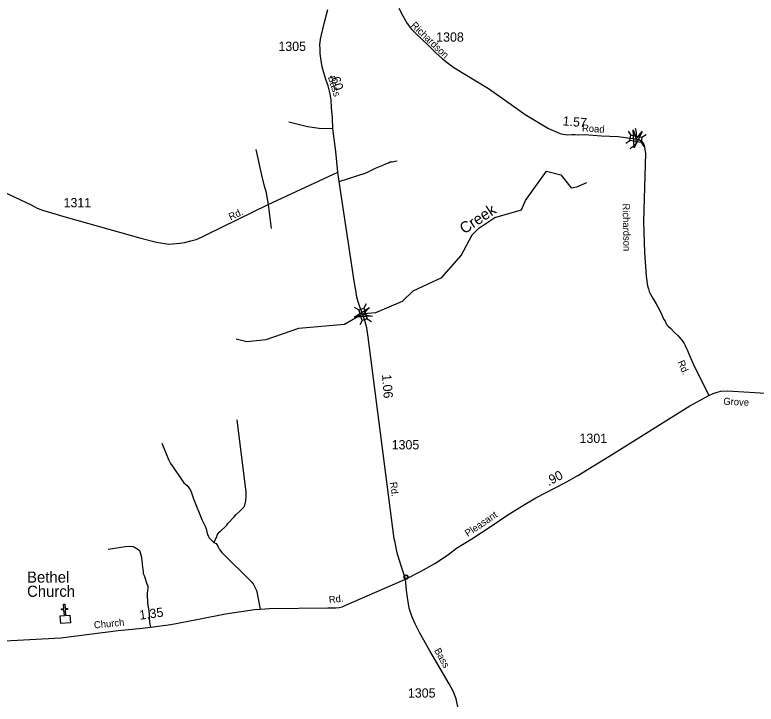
# Model space of a CAD drawing. Extents: x 2220236 to 2384410, y 720751 to 894131.
# Drawn here: x 2267334 to 2277319, y 812774 to 822056 of the extents above; entities that cross this region are included whole.
import ezdxf

# ---------------------------------------------------------------- set-up
doc = ezdxf.new("R2010")
doc.units = 0
doc.layers.add('Default', color=7, linetype='Continuous')

msp = doc.modelspace()

# ---------------------------------------------------------------- linework, layer by layer
at = {"layer": 'Default'}
for p, q in [((2275592.8, 820491.3), (2275632, 820434.5)), ((2275780.5, 820406.9), (2275837.3, 820446.1)), ((2275562.4, 820325.9), (2275619.2, 820365.1)), ((2275768.1, 820339.1), (2275807.3, 820282.3)), ((2270747.9, 819500.1), (2270784.5, 819176.6)), ((2271906.2, 818117.7), (2271967, 818085.1)), ((2272067.2, 818166.3), (2272034.6, 818105.5)), ((2272011.9, 817940.8), (2271979.3, 817880)), ((2272078, 817960.8), (2272138.8, 817928.2))]:
    msp.add_line(p, q, dxfattribs=at)
for points in [[(2271686.2, 819937.3), (2271658.4, 820215.3), (2271618, 820518.6), (2271611.2, 820668.5), (2271599.4, 820806.7), (2271594.4, 820906.1), (2271580.9, 820993.7), (2271554, 821098.2), (2271522, 821185.8), (2271496.7, 821276.8), (2271473.2, 821354.3), (2271459.7, 821441.9), (2271447.9, 821534.5), (2271444.5, 821595.2), (2271442.9, 821650.8), (2271452.1, 821728.3), (2271463.9, 821785.6), (2271499.3, 821940.6), (2271549.2, 822126.5)], [(2272504.9, 822144.5), (2272560, 822040.1), (2272619, 821937.8), (2272676.1, 821861), (2272741, 821798), (2272902.3, 821646.4), (2273004.6, 821546), (2273093.2, 821463.3), (2273158.1, 821412.1), (2273244.7, 821347.2), (2273712.9, 821065.6), (2274049.3, 820827.4), (2274208.7, 820715.2), (2274364.2, 820621.4), (2274523, 820527.1), (2274676.9, 820457.3), (2274713.3, 820447.5), (2274751.7, 820443.5), (2274783.2, 820441.6), (2274835.5, 820444), (2274879.6, 820444.3), (2274920.6, 820441.9), (2275008.8, 820443), (2275237.7, 820428), (2275461.5, 820415.8), (2275687.5, 820388.2)], [(2271618, 820518.6), (2271433.6, 820523.6), (2271277, 820546.4), (2271024.5, 820609.6)], [(2275690.7, 820531.3), (2275694.3, 820514.9), (2275698.7, 820490.8), (2275700.8, 820466.2), (2275701.2, 820450.8), (2275700.6, 820385.2), (2275700.1, 820350.8), (2275701.2, 820343.2), (2275701.1, 820337.6), (2275700.3, 820331.1), (2275694.4, 820316.4), (2275686.3, 820304.1), (2275674.9, 820292.2), (2275658.6, 820280.1), (2275637, 820265.8), (2275621, 820253)], [(2275687.5, 820388.2), (2275742.9, 820375.2), (2275778.8, 820349.1), (2275800.7, 820319.9), (2275810.8, 820295.9), (2275826.9, 820191.6), (2275800.1, 819271.5), (2275813.9, 818855.9), (2275835.1, 818536.2), (2275856.2, 818406.6), (2275866.6, 818364.6), (2275879, 818328.7), (2275895.3, 818292.8), (2275930.2, 818230.8), (2275971.5, 818165.8), (2276027.6, 818065.4), (2276074.4, 817954.8), (2276091, 817929.6), (2276113, 817887.2), (2276133.1, 817863.4), (2276167.5, 817831.7), (2276217.9, 817778.1), (2276266.4, 817734.7), (2276312.9, 817681.2), (2276331, 817659.4), (2276347.2, 817629.5), (2276363.5, 817603.5), (2276382, 817561.8), (2276396.2, 817533.9), (2276420.9, 817468.2), (2276469.9, 817354.8), (2276681.8, 816929)], [(2270581.2, 820240.6), (2270657, 819896.9), (2270689.8, 819765.5), (2270715.1, 819679.6), (2270732.7, 819578.5), (2270747.9, 819500.1)], [(2271701.1, 819812.7), (2272063.8, 819930.2), (2272193.2, 819989.3), (2272282.8, 820026.2), (2272338.5, 820054.6), (2272368.5, 820065), (2272390.4, 820077.2), (2272416.4, 820077.4), (2272454.1, 820085.6), (2272484.2, 820090)], [(2266879.9, 819811), (2267556.1, 819497.9), (2267635.1, 819452.1), (2267708.3, 819426.8), (2268024, 819330.8), (2269029.2, 819050.3), (2269243.9, 818994.7), (2269406.8, 818969.4), (2269554.6, 818982), (2269620.2, 818992.2), (2269703.6, 819014.9), (2269774.3, 819032.6), (2269849.2, 819061.8), (2269918.7, 819098.4), (2270747.9, 819500.1), (2271686.2, 819937.3)], [(2270317.1, 817694.8), (2270459.2, 817655.8), (2270717.1, 817683.3), (2271157.2, 817834.9), (2271773.2, 817891), (2271976, 818007.4), (2272022.2, 818022), (2272088.9, 818036.5), (2272196.2, 818046.2), (2272553.2, 818199.6), (2272701.2, 818340.9), (2273083, 818519.9), (2273347.2, 818816.2), (2273494.2, 819092), (2273585.2, 819185.2), (2273800.1, 819328.3), (2274157.1, 819429.2), (2274214.1, 819555.9), (2274494.2, 819950.3), (2274686.1, 819900.4), (2274829.1, 819726.9), (2274904.1, 819738.4), (2275039.7, 819799)], [(2272016.9, 818020.7), (2271958.3, 818189.8), (2271939.7, 818255.8), (2271928.8, 818347.6), (2271909.9, 818443.4), (2271701.1, 819812.7), (2271686.2, 819937.3)], [(2272596.2, 814458.7), (2272506.5, 814734.7), (2272481.7, 814812.4), (2272454.5, 814950.1), (2272442, 815000), (2272094.7, 817717.4), (2272073.4, 817839.2), (2272046.5, 817940.9), (2272028.1, 817988.7), (2272016.9, 818020.7)], [(2276681.8, 816929), (2276739.4, 816955.6), (2276781.3, 816971.9), (2276843.2, 816986.4), (2276931, 816991.2), (2278110.9, 816921.9), (2278135.2, 816920.5), (2278839.2, 816881.2), (2278925.2, 816874), (2279263.1, 816857.2), (2279327.2, 816859.9), (2279464.8, 816883), (2279580.7, 816906.2), (2280106.9, 817043.1), (2280285.4, 817103.6), (2280420.8, 817153), (2280532.1, 817191.4), (2280657.6, 817236.5)], [(2272596.2, 814458.7), (2272796.3, 814560.7), (2272990.7, 814669.2), (2273160.5, 814781.6), (2273284.7, 814874), (2273490.8, 815001.6), (2273762.6, 815181), (2273960.7, 815313.2), (2274160.8, 815439.7), (2274352, 815551.7), (2274741.9, 815755.2), (2274916.7, 815850.8), (2275336.1, 816110.6), (2276425.3, 816790.5), (2276681.8, 816929)], [(2270015.7, 814949.2), (2270050.9, 815019.4), (2270060.7, 815047.6), (2270074.4, 815073.7), (2270084.3, 815087.7), (2270108.2, 815110), (2270173.5, 815164.6), (2270189.5, 815182.7), (2270201.1, 815204.9), (2270286.2, 815295.5), (2270315.9, 815329.8), (2270361.5, 815370.3), (2270418.9, 815428.7), (2270430.8, 815452.8), (2270446.2, 815512.9), (2270449.5, 815575), (2270449, 815629), (2270330, 816603.4)], [(2269313.4, 816289.9), (2269405.4, 816068.9), (2269431.9, 816015.1), (2269468.3, 815965.6), (2269567.7, 815812.6), (2269610.3, 815754.9), (2269654.7, 815717.4), (2269699.2, 815655.9), (2269719.7, 815604.1), (2269742.2, 815538.2), (2269854.8, 815261.6), (2269895.5, 815172), (2269909.9, 815134.1), (2269928.7, 815054.3), (2269940.9, 815036.5), (2269949.1, 815016.5), (2270015.7, 814949.2)], [(2268589.1, 814861.9), (2268820.8, 814895.9), (2268876.6, 814900.5), (2268924.7, 814894.9), (2268956.9, 814883.3), (2268982.9, 814867.5), (2269011.2, 814841.8), (2269037.7, 814772), (2269046.5, 814710.3), (2269055.2, 814618.3), (2269061.7, 814566.4), (2269062, 814532.4), (2269074.2, 814506.6), (2269115.5, 814382.9), (2269123.6, 814369), (2269123.9, 814337), (2269122.1, 814299), (2269118.5, 814269.1), (2269117, 814217.2), (2269121.5, 814171.1), (2269121.7, 814133.1), (2269132.4, 814059.3), (2269145.2, 813991.4), (2269143.5, 813941.5), (2269148.2, 813875.6), (2269162.8, 813811.7)], [(2270015.7, 814949.2), (2270043.8, 814935.4), (2270068.1, 814899.7), (2270078.2, 814879.9), (2270086.4, 814869.9), (2270104.6, 814840.2), (2270122.9, 814816.2), (2270524.5, 814416.2), (2270542.6, 814392.4), (2270562.9, 814356.6), (2270587.6, 814302.9), (2270597.8, 814264.9), (2270608.3, 814215.1), (2270637.8, 814053.4)], [(2267115.6, 813621.1), (2267951.6, 813669.3), (2268727.3, 813767.5), (2269053, 813796.6), (2269162.8, 813811.7), (2269436.3, 813846.3), (2269808.7, 813920.4), (2270173, 813988.4), (2270561.9, 814048.7), (2270637.8, 814053.4), (2270765.7, 814062.7), (2271551.2, 814070.1), (2271659.2, 814069), (2271701.1, 814073.4), (2271742.9, 814083.9), (2271800.6, 814112.3), (2272596.2, 814458.7)], [(2273300.2, 812740.2), (2273287, 812802.5), (2273277.5, 812844), (2273237, 812950.4), (2273181.9, 813045.9), (2272922.7, 813490.8), (2272783.1, 813739.2), (2272724.6, 813854.4), (2272683, 813958.2), (2272647.2, 814067.8), (2272620.8, 814209.4), (2272609.4, 814307.6), (2272596.2, 814458.7)]]:
    msp.add_lwpolyline(points, dxfattribs=at)
for points in [[(2275784.4, 820484.6), (2275677.1, 820265.6), (2275660.5, 820508.9), (2275700.6, 820385.2)], [(2275632, 820434.5), (2275780.6, 820407.2), (2275767.8, 820337.8), (2275619.2, 820365.1)], [(2272149.6, 817996.3), (2271906, 817984.9), (2272111.2, 818116.6), (2272022.2, 818022)], [(2272034.6, 818105.5), (2272078.3, 817960.9), (2272010.7, 817940.5), (2271967, 818085.1)], [(2272579, 814489.6), (2272579.3, 814491.3), (2272579.8, 814493.3), (2272580.7, 814495.5), (2272581.6, 814497.2), (2272582.6, 814499), (2272583.8, 814500.5), (2272585, 814501.9), (2272586.4, 814503.3), (2272588.1, 814504.7), (2272589.7, 814505.8), (2272591.2, 814506.6), (2272592.8, 814507.4), (2272594.4, 814508.1), (2272596.1, 814508.6), (2272597.5, 814509), (2272598.9, 814509.2), (2272600.2, 814509.4), (2272602.1, 814509.5), (2272603.5, 814509.5), (2272605.2, 814509.4), (2272606.7, 814509.2), (2272608.2, 814508.9), (2272609.7, 814508.5), (2272611.3, 814507.9), (2272613.3, 814507), (2272615.2, 814505.9), (2272616.8, 814504.8), (2272618.4, 814503.6), (2272619.4, 814502.6), (2272620.6, 814501.3), (2272621.8, 814499.9), (2272622.7, 814498.5), (2272623.7, 814497), (2272624.4, 814495.4), (2272625.1, 814493.9), (2272625.5, 814492.3), (2272625.9, 814490.9), (2272626.3, 814489.1), (2272626.5, 814487.7), (2272626.5, 814485.8), (2272626.5, 814484.1), (2272626.3, 814482.3), (2272626, 814480.7), (2272625.5, 814478.8), (2272624.9, 814477), (2272624.2, 814475.5), (2272623.3, 814473.6), (2272622.3, 814472), (2272621.2, 814470.6), (2272619.9, 814469.1), (2272618.3, 814467.6), (2272616.8, 814466.4), (2272615.3, 814465.3), (2272614, 814464.5), (2272611.9, 814463.6), (2272609.7, 814462.7), (2272607.9, 814462.3), (2272605.9, 814461.9), (2272604.5, 814461.7), (2272603.2, 814461.7), (2272601.5, 814461.7), (2272600.2, 814461.8), (2272598.4, 814462), (2272596.6, 814462.4), (2272595.2, 814462.8), (2272593.7, 814463.4), (2272592.3, 814464), (2272591.1, 814464.7), (2272589, 814465.9), (2272587.3, 814467.2), (2272585.8, 814468.6), (2272584.4, 814470.1), (2272583.5, 814471.3), (2272582.6, 814472.5), (2272581.3, 814474.7), (2272580.8, 814475.8), (2272580.3, 814477), (2272579.5, 814479.5), (2272579, 814481.7), (2272578.8, 814483.2), (2272578.7, 814485.2), (2272578.7, 814486.6), (2272578.8, 814488.6)], [(2272579, 814489.6), (2272579.3, 814491.3), (2272579.8, 814493.3), (2272580.7, 814495.5), (2272581.6, 814497.2), (2272582.6, 814499), (2272583.8, 814500.5), (2272585, 814501.9), (2272586.4, 814503.3), (2272588.1, 814504.7), (2272589.7, 814505.8), (2272591.2, 814506.6), (2272592.8, 814507.4), (2272594.4, 814508.1), (2272596.1, 814508.6), (2272597.5, 814509), (2272598.9, 814509.2), (2272600.2, 814509.4), (2272602.1, 814509.5), (2272603.5, 814509.5), (2272605.2, 814509.4), (2272606.7, 814509.2), (2272608.2, 814508.9), (2272609.7, 814508.5), (2272611.3, 814507.9), (2272613.3, 814507), (2272615.2, 814505.9), (2272616.8, 814504.8), (2272618.4, 814503.6), (2272619.4, 814502.6), (2272620.6, 814501.3), (2272621.8, 814499.9), (2272622.7, 814498.5), (2272623.7, 814497), (2272624.4, 814495.4), (2272625.1, 814493.9), (2272625.5, 814492.3), (2272625.9, 814490.9), (2272626.3, 814489.1), (2272626.5, 814487.7), (2272626.5, 814485.8), (2272626.5, 814484.1), (2272626.3, 814482.3), (2272626, 814480.7), (2272625.5, 814478.8), (2272624.9, 814477), (2272624.2, 814475.5), (2272623.3, 814473.6), (2272622.3, 814472), (2272621.2, 814470.6), (2272619.9, 814469.1), (2272618.3, 814467.6), (2272616.8, 814466.4), (2272615.3, 814465.3), (2272614, 814464.5), (2272611.9, 814463.6), (2272609.7, 814462.7), (2272607.9, 814462.3), (2272605.9, 814461.9), (2272604.5, 814461.7), (2272603.2, 814461.7), (2272601.5, 814461.7), (2272600.2, 814461.8), (2272598.4, 814462), (2272596.6, 814462.4), (2272595.2, 814462.8), (2272593.7, 814463.4), (2272592.3, 814464), (2272591.1, 814464.7), (2272589, 814465.9), (2272587.3, 814467.2), (2272585.8, 814468.6), (2272584.4, 814470.1), (2272583.5, 814471.3), (2272582.6, 814472.5), (2272581.3, 814474.7), (2272580.8, 814475.8), (2272580.3, 814477), (2272579.5, 814479.5), (2272579, 814481.7), (2272578.8, 814483.2), (2272578.7, 814485.2), (2272578.7, 814486.6), (2272578.8, 814488.6)], [(2267944.8, 813964.5), (2268001.6, 813968.6), (2267996.1, 814044.6), (2267964.2, 814042.3), (2267963.1, 814058.2), (2267995, 814060.5), (2267990.7, 814120.5), (2268006.7, 814121.6), (2268011, 814061.7), (2268042.9, 814063.9), (2268044, 814048), (2268012.1, 814045.7), (2268017.5, 813969.8), (2268075.1, 813973.8), (2268082.6, 813867.6), (2267952.4, 813858.3)]]:
    msp.add_lwpolyline(points, close=True, dxfattribs=at)
for centre, radius in [((2272602.7, 814485.8), 28.8), ((2272602.7, 814485.8), 28.8), ((2272602.6, 814485.9), 23.4), ((2272602.6, 814485.9), 23.4)]:
    msp.add_circle(centre, radius, dxfattribs=at)

# ---------------------------------------------------------------- texts
for s, height, rotation, p in [('Richardson', 95, 316.15961, (2272661.7, 821904.7)), ('Bass', 95, 287.21735, (2271550.1, 821215.8)), ('.60', 125, 287.85775, (2271575.1, 821245.8)), ('1.57', 125, 354.82839, (2274708.6, 820567.9)), ('Road', 95, 356.31158, (2274971, 820486)), ('Creek', 150, 33.66503, (2273387.5, 819098.2)), ('Richardson', 95, 271.0871, (2275519.4, 819514.8)), ('Rd.', 95, 25.28224, (2270240.7, 819286.8)), ('Rd.', 95, 293.37042, (2276257.7, 817380.2)), ('1.06', 125, 274.35729, (2272279, 817211.8)), ('Grove', 95, 357.50052, (2276875.2, 816805.8)), ('.90', 125, 27.56133, (2274523.9, 815709.4)), ('Rd.', 95, 277.28326, (2272386.1, 815760.5)), ('Pleasant', 95, 34.04977, (2273434.5, 815024.8)), ('Rd.', 95, 6.61296, (2271568.4, 814132)), ('1.35', 125, 7.83124, (2269019.2, 813909.4)), ('Church', 95, 5.577, (2268404.2, 813792.1)), ('Bass', 95, 298.93223, (2272979.1, 813497.5))]:
    msp.add_text(s, height=height, rotation=rotation, dxfattribs=at).set_placement(p)
for s, height, p in [('1308', 125, (2273009.1, 821694.3)), ('1305', 125, (2270884, 821569.4)), ('1311', 125, (2267990.3, 819464.3)), ('1301', 125, (2274939.8, 816291.4)), ('1305', 125, (2272409.2, 816204.3)), ('Bethel', 150, (2267498.7, 814410.1)), ('Church', 150, (2267498.7, 814219.1)), ('1305', 125, (2272628.4, 812861.9))]:
    msp.add_text(s, height=height, dxfattribs=at).set_placement(p)

doc.saveas('drawing.dxf')
